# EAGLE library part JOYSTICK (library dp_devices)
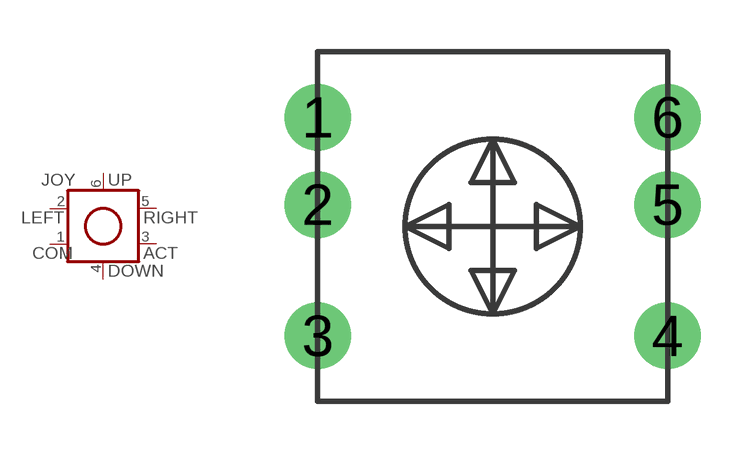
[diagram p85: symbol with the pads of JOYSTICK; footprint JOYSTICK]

Designator prefix JOY

## JOYSTICK  [JOYSTICK]
1  COM
2  LEFT
3  ACT
4  DOWN
5  RIGHT
6  UP

## Footprint JOYSTICK (pad centres in mm)
drill 1 pad 1.93 round: 1 -5.08,3.175; 3 -5.08,-3.175; 4 5.08,-3.175; 6 5.08,3.175
drill 0.8 pad 1.93 round: 2 -5.08,0.635; 5 5.08,0.635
